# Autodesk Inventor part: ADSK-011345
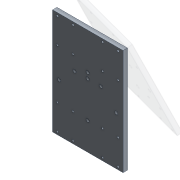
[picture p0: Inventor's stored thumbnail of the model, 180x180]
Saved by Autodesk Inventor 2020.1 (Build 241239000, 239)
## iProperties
Created: 1999-11
Part Number: ADSK-011345
Material: Pearson Aluminium
Document SubType Name: Modeling
Designer: glanglot
Density: 2.71 g/cm^3
Appearance: Pearson-Aluminum
Mass: 2069.41 g
Surface Area: 1408.09 cm^2
Volume: 763.619 cm^3
Control State: 0
Master: False
Checked Out: False
Shininess: 35.0
Length Units: 11269
Angle Units: 11279
Time Units: 11290
Mass Units: 11283
Length Display Precision: 3
Angle Display Precision: 2
Compacted: True
CUTLENGTH: 12
MATERIAL DESC: FLAT,ALUM,0.50 X 8.00
MATERIAL_NUMBER: A084017
Dimensions: 203x305x12,5 mm
Mass: 2,069 kg
DocNumber: ADSK-011345.ipt
Folder: 01 - Themengebiete\Simplification\01 - Packaging machine\
VDS_Category: 3D Komponenten
Density: 2.71
Volumn: 775.2169485116747
Area: 1410.9676818105054
PropertySet Name: Model Information
Author: glanglot
Revision Number: -
Title: base plate
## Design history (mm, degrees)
node "Solide1"
  node "Extrusion1" dims "d0" = 12.5, "d1" = 0
  node "Hole1" dims "d12" = 5.5, "d13" = 9.525, "d14" = 6.35, "d15" = 60 deg, "d16" = 19.05, "d17" = 118 deg, "d95" = 6
  node "Hole2" dims "d57" = 9, "d58" = 9.525, "d59" = 6.35, "d60" = 60 deg, "d61" = 19.05, "d62" = 118 deg, "d98" = 6
  node "Hole3" dims "d63" = 9, "d64" = 9.525, "d65" = 6.35, "d66" = 60 deg, "d67" = 19.05, "d68" = 118 deg, "d102" = 6
  node "Hole4" dims "d77" = 9, "d78" = 9.525, "d79" = 6.35, "d80" = 60 deg, "d81" = 19.05, "d82" = 118 deg, "d103" = 6
sketch "Sketch1"
  geometry: L1 (-101.5, 152.5)-(101.5, 152.5); L2 (101.5, 152.5)-(101.5, -152.5); L3 (101.5, -152.5)-(-101.5, -152.5); L4 (-101.5, -152.5)-(-101.5, 152.5); 3 further points
  constraints: 8 end point, 2 midpoint, 2 parallel, 1 horizontal, 1 horizontal alignment, 1 perpendicular, 1 vertical alignment
  dimensions: "d2" = 305 distance of L3.end L1.start; "d3" = 203 distance of L1.start L1.end
sketch "Sketch2"
  geometry: L1 (101.5, 152.5)-(101.5, -152.5) reference; L2 (-101.5, 152.5)-(101.5, 152.5) reference; L3 (-101.5, -152.5)-(-101.5, 152.5) reference; L4 (101.5, -152.5)-(-101.5, -152.5) reference; L5 (42.5, -71.5)-(87.5, -71.5); L6 (87.5, -71.5)-(87.5, -144.5); L7 (87.5, -144.5)-(42.5, -144.5); L8 (42.5, -144.5)-(42.5, -71.5); L9 (-101.5, 0)-(101.5, 0); L10 (0, 152.5)-(0, -152.5); L11 (-87.5, -71.5)-(-42.5, -71.5); L12 (-42.5, -71.5)-(-42.5, -144.5); L13 (-42.5, -144.5)-(-87.5, -144.5); L14 (-87.5, -144.5)-(-87.5, -71.5); L15 (-87.5, 144.5)-(-42.5, 144.5); L16 (-42.5, 144.5)-(-42.5, 71.5); L17 (-42.5, 71.5)-(-87.5, 71.5); L18 (-87.5, 71.5)-(-87.5, 144.5); L19 (42.5, 144.5)-(87.5, 144.5); L20 (87.5, 144.5)-(87.5, 71.5); L21 (87.5, 71.5)-(42.5, 71.5); L22 (42.5, 71.5)-(42.5, 144.5); L23 (-65, 144.5)-(-65, 71.5); L24 (65, 144.5)-(65, 71.5); L25 (65, -71.5)-(65, -144.5); L26 (-65, -71.5)-(-65, -144.5); 8 further points
  constraints: 44 end point, 12 midpoint, 8 coincident, 8 parallel, 5 collinear, 4 horizontal, 4 perpendicular
  dimensions: "d83" = 73 distance of L19.end L20.end; "d84" = 45 distance of L19.start L19.end; "d85" = 71.5 distance between parallel lines of L9 L21; "d87" = 130 distance between parallel lines of L23 L24; "d88" = 65 distance between parallel lines of L10 L24 (= 0.5 x d87); "d89" = 71.5 distance between parallel lines of L9 L5 (= d85); "d90" = 45 distance of L15.start L15.end (= d84); "d91" = 45 distance of L6.end L7.end (= d84); "d92" = 45 distance of L12.end L13.end (= d84); "d93" = 73 distance of L5.end L6.end (= d83); "d94" = 73 distance of L13.end L11.start (= d83)
sketch "Sketch3"
  geometry: L1 (-101.5, 152.5)-(101.5, 152.5) reference; L2 (-38, 31.5)-(38, 31.5); L3 (101.5, -152.5)-(-101.5, -152.5) reference; 3 further points
  constraints: 2 end point, 2 midpoint, 1 coincident, 1 horizontal, 1 vertical alignment
  dimensions: "d96" = 76 distance of L2.start L2.end; "d97" = 184 distance between parallel lines of L3 L2
sketch "Sketch4"
  geometry: L1 (101.5, -152.5)-(-101.5, -152.5) reference; L2 (0, 47.5)-(0, -72.5); L3 (-82.5, -12.5)-(82.5, -12.5); 4 further points
  constraints: 5 midpoint, 4 end point, 2 vertical alignment, 1 horizontal, 1 vertical
  dimensions: "d99" = 140 distance between parallel lines of L1 L3; "d100" = 165 distance of L3.start L3.end; "d101" = 120 distance of L2.start L2.end
node "Corps solides"
node "Corps surfaciques"
feature "耀䀮"
